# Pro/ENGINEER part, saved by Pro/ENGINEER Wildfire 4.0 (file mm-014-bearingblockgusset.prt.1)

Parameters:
  METRIC = "NO"

Other parameters: PITCH, DRILL_POINT_ANGLE, DRILL_DEPTH, DRILL_DIAMETER, THREAD_DIAMETER, THREADS_PER_INCH, THREAD_DEPTH, THREAD_LENGTH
